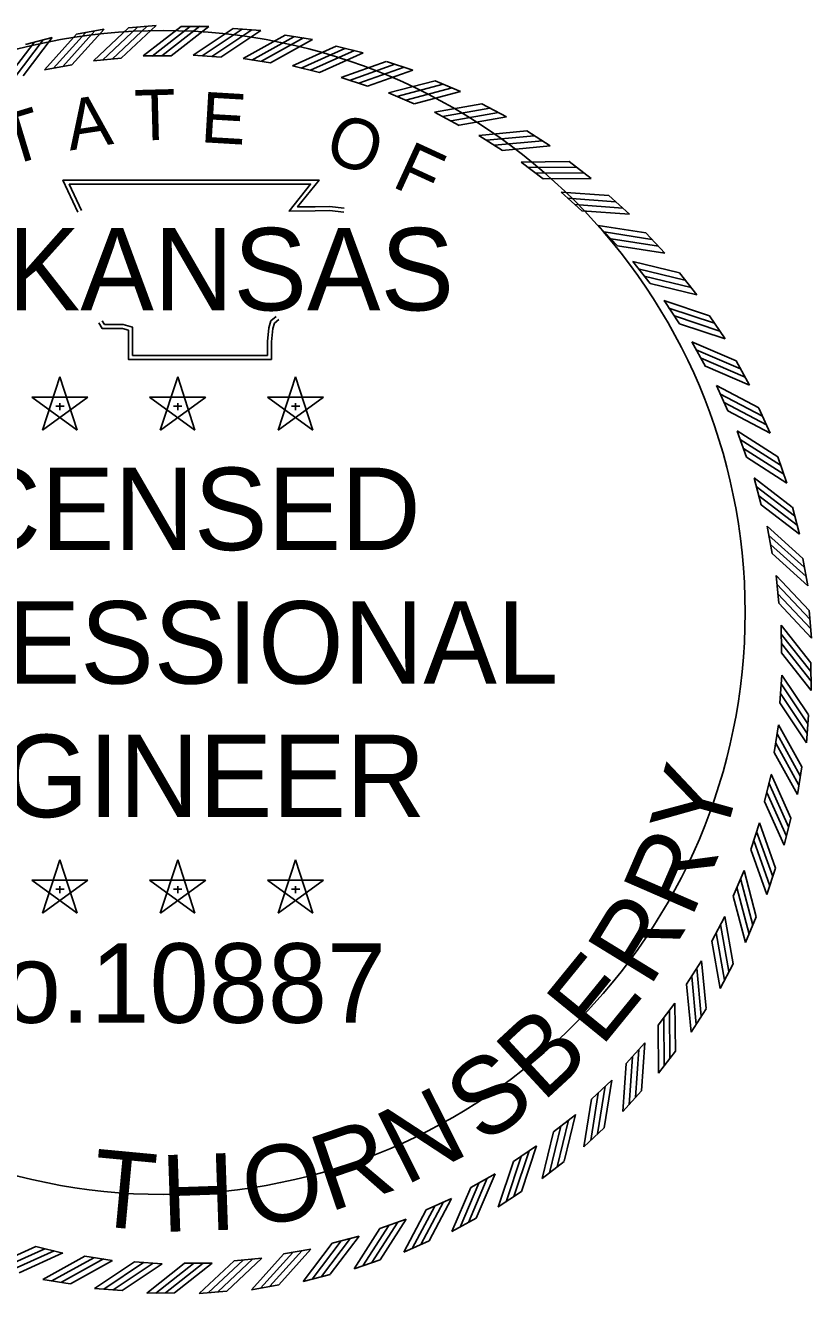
# Model space of a CAD drawing. Extents: x 152 to 3426, y 67 to 2142.
# Drawn here: x 3095.4 to 3247.4, y 306.4 to 551.5 of the extents above; entities that cross this region are included whole.
import ezdxf

# ---------------------------------------------------------------- set-up
doc = ezdxf.new("R2010")
doc.units = 0
doc.layers.add('G-TBLK', color=7, linetype='Continuous')
doc.layers.add('R_Annotation', color=7, linetype='Continuous')

msp = doc.modelspace()

# ---------------------------------------------------------------- linework, layer by layer
at = {"layer": 'G-TBLK'}
msp.add_circle((3122.09, 438.03), 112.43, dxfattribs=at)
at = {"layer": 'R_Annotation'}
for p, q in [((3115.38, 550.96), (3120.73, 551.45)), ((3095.43, 547.73), (3100.62, 549.1)), ((3105.34, 549.76), (3110.62, 550.69)), ((3125.54, 551.26), (3130.91, 551.26)), ((3135.59, 550.85), (3140.95, 550.46)), ((3135.6, 550.86), (3140.95, 550.47)), ((3145.62, 549.55), (3150.92, 548.72)), ((3155.51, 547.43), (3160.73, 546.16)), ((3108.61, 544.6), (3113.97, 545.09)), ((3118.22, 545.55), (3123.6, 545.55)), ((3127.87, 545.7), (3133.24, 545.3)), ((3127.87, 545.7), (3133.24, 545.3)), ((3137.5, 545.05), (3142.82, 544.21)), ((3165.19, 544.49), (3170.28, 542.8)), ((3099.12, 542.86), (3104.42, 543.8)), ((3147.05, 543.61), (3152.27, 542.34)), ((3156.44, 541.39), (3161.54, 539.69)), ((3174.6, 540.77), (3179.53, 538.66)), ((3165.62, 538.4), (3170.56, 536.28)), ((3174.52, 534.66), (3179.27, 532.14)), ((3183.66, 536.28), (3188.4, 533.77)), ((3183.08, 530.2), (3187.61, 527.3)), ((3192.32, 531.06), (3196.84, 528.16)), ((3191.24, 525.04), (3195.51, 521.78)), ((3200.52, 525.14), (3204.79, 521.88)), ((3198.95, 519.23), (3202.94, 515.63)), ((3208.21, 518.56), (3212.19, 514.96)), ((3206.15, 512.81), (3209.83, 508.88)), ((3215.32, 511.37), (3218.99, 507.46)), ((3212.8, 505.81), (3216.14, 501.59)), ((3221.82, 503.62), (3225.16, 499.42)), ((3218.85, 498.28), (3221.83, 493.81)), ((3227.66, 495.36), (3230.63, 490.89)), ((3224.25, 490.29), (3226.85, 485.58)), ((3232.79, 486.64), (3235.39, 481.95)), ((3102.1, 483.56), (3098.74, 473.26)), ((3105.44, 473.26), (3102.1, 483.57)), ((3124.86, 483.56), (3121.5, 473.26)), ((3128.2, 473.26), (3124.86, 483.57)), ((3147.62, 483.56), (3144.26, 473.26)), ((3150.96, 473.26), (3147.62, 483.57)), ((3228.98, 481.87), (3231.18, 476.96)), ((3107.51, 479.62), (3096.67, 479.63)), ((3096.68, 479.62), (3105.44, 473.25)), ((3098.75, 473.26), (3107.52, 479.62)), ((3101.32, 477.89), (3102.93, 477.89)), ((3102.11, 478.47), (3102.11, 477.11)), ((3130.27, 479.62), (3119.43, 479.63)), ((3119.44, 479.62), (3128.2, 473.25)), ((3121.51, 473.26), (3130.28, 479.62)), ((3124.08, 477.89), (3125.69, 477.89)), ((3124.87, 478.47), (3124.87, 477.11)), ((3153.03, 479.62), (3142.19, 479.63)), ((3142.2, 479.62), (3150.96, 473.25)), ((3144.27, 473.26), (3153.04, 479.62)), ((3146.84, 477.89), (3148.45, 477.89)), ((3147.63, 478.47), (3147.63, 477.11)), ((3237.19, 477.53), (3239.39, 472.64)), ((3232.99, 473.09), (3234.78, 468.02)), ((3240.82, 468.09), (3242.6, 463.03)), ((3236.27, 464.01), (3237.64, 458.81)), ((3243.65, 458.38), (3245.02, 453.19)), ((3238.78, 454.69), (3239.72, 449.4)), ((3245.68, 448.47), (3246.61, 443.19)), ((3240.52, 445.2), (3241.01, 439.84)), ((3246.88, 438.43), (3247.37, 433.09)), ((3241.47, 435.59), (3241.52, 430.21)), ((3247.24, 428.32), (3247.29, 422.96)), ((3241.62, 425.94), (3241.22, 420.58)), ((3246.77, 418.22), (3246.38, 412.87)), ((3240.97, 416.31), (3240.13, 411)), ((3239.53, 406.76), (3238.26, 401.54)), ((3245.47, 408.19), (3244.64, 402.89)), ((3237.31, 397.37), (3235.61, 392.27)), ((3243.35, 398.3), (3242.08, 393.09)), ((3102.1, 390.24), (3098.74, 379.94)), ((3105.44, 379.94), (3102.1, 390.25)), ((3124.86, 390.24), (3121.5, 379.94)), ((3128.2, 379.94), (3124.86, 390.25)), ((3147.62, 390.24), (3144.26, 379.94)), ((3150.96, 379.94), (3147.62, 390.25)), ((3234.31, 388.19), (3232.2, 383.25)), ((3240.41, 388.62), (3238.71, 383.53)), ((3107.51, 386.3), (3096.67, 386.31)), ((3096.68, 386.3), (3105.44, 379.93)), ((3098.75, 379.94), (3107.52, 386.3)), ((3102.11, 385.15), (3102.11, 383.79)), ((3130.27, 386.3), (3119.43, 386.31)), ((3119.44, 386.3), (3128.2, 379.93)), ((3121.51, 379.94), (3130.28, 386.3)), ((3124.87, 385.15), (3124.87, 383.79)), ((3153.03, 386.3), (3142.19, 386.31)), ((3142.2, 386.3), (3150.96, 379.93)), ((3144.27, 379.94), (3153.04, 386.3)), ((3147.63, 385.15), (3147.63, 383.79)), ((3101.32, 384.57), (3102.93, 384.57)), ((3124.08, 384.57), (3125.69, 384.57)), ((3146.84, 384.57), (3148.45, 384.57)), ((3230.58, 379.3), (3228.06, 374.54)), ((3236.68, 379.22), (3234.57, 374.28)), ((3226.11, 370.74), (3223.21, 366.21)), ((3232.2, 370.15), (3229.69, 365.41)), ((3220.96, 362.57), (3217.7, 358.3)), ((3226.97, 361.49), (3224.08, 356.97)), ((3215.15, 354.86), (3211.55, 350.87)), ((3221.06, 353.29), (3217.8, 349.02)), ((3208.73, 347.66), (3204.8, 343.98)), ((3214.48, 345.6), (3210.88, 341.62)), ((3201.73, 341.01), (3197.51, 337.67)), ((3207.29, 338.49), (3203.38, 334.82)), ((3194.2, 334.97), (3189.73, 331.98)), ((3199.54, 331.99), (3195.33, 328.66)), ((3186.21, 329.56), (3181.5, 326.96)), ((3191.28, 326.15), (3186.81, 323.18)), ((3177.79, 324.84), (3172.88, 322.63)), ((3182.56, 321.02), (3177.87, 318.42)), ((3169.01, 320.82), (3163.94, 319.03)), ((3159.93, 317.55), (3154.73, 316.18)), ((3173.45, 316.63), (3168.56, 314.43)), ((3102.68, 314.28), (3097.46, 315.55)), ((3112.23, 312.84), (3106.92, 313.68)), ((3150.61, 315.03), (3145.32, 314.1)), ((3121.86, 312.2), (3116.5, 312.59)), ((3131.51, 312.35), (3126.13, 312.3)), ((3141.12, 313.29), (3135.76, 312.8)), ((3164.01, 313), (3158.95, 311.21)), ((3104.11, 308.34), (3098.81, 309.18)), ((3154.3, 310.16), (3149.11, 308.8)), ((3114.14, 307.04), (3108.79, 307.43)), ((3124.24, 306.57), (3118.88, 306.52)), ((3134.35, 306.94), (3129.01, 306.44)), ((3144.39, 308.14), (3139.11, 307.2))]:
    msp.add_line(p, q, dxfattribs=at)
for points in [[(3112.18, 544.95), (3118.95, 551.31)], [(3113.96, 545.1), (3120.73, 551.45)], [(3094.99, 541.72), (3100.62, 549.1)], [(3099.11, 542.86), (3105.33, 549.75)], [(3100.82, 543.14), (3107.04, 550.04)], [(3102.65, 543.51), (3108.86, 550.4)], [(3104.41, 543.8), (3110.63, 550.69)], [(3108.61, 544.59), (3115.37, 550.95)], [(3110.33, 544.74), (3117.1, 551.09)], [(3118.21, 545.54), (3125.54, 551.25)], [(3119.94, 545.53), (3127.26, 551.24)], [(3121.81, 545.57), (3129.13, 551.28)], [(3123.59, 545.55), (3130.91, 551.26)], [(3127.86, 545.69), (3135.59, 550.86)], [(3127.87, 545.69), (3135.59, 550.85)], [(3129.58, 545.55), (3137.31, 550.71)], [(3129.59, 545.55), (3137.31, 550.71)], [(3131.45, 545.46), (3139.18, 550.62)], [(3131.45, 545.45), (3139.17, 550.61)], [(3133.23, 545.31), (3140.96, 550.47)], [(3133.23, 545.31), (3140.95, 550.46)], [(3137.5, 545.05), (3145.62, 549.55)], [(3139.2, 544.76), (3147.32, 549.26)], [(3141.05, 544.51), (3149.17, 549.02)], [(3091.47, 540.77), (3097.1, 548.15)], [(3093.26, 541.28), (3098.89, 548.66)], [(3142.81, 544.22), (3150.93, 548.72)], [(3147.04, 543.61), (3155.5, 547.42)], [(3148.71, 543.18), (3157.18, 547)], [(3150.54, 542.78), (3159, 546.6)], [(3152.27, 542.34), (3160.73, 546.16)], [(3156.43, 541.38), (3165.18, 544.49)], [(3158.07, 540.82), (3166.82, 543.93)], [(3159.85, 540.27), (3168.6, 543.38)], [(3161.54, 539.69), (3170.29, 542.8)], [(3165.61, 538.39), (3174.59, 540.76)], [(3167.19, 537.7), (3176.17, 540.07)], [(3168.92, 537), (3177.9, 539.38)], [(3170.56, 536.29), (3179.54, 538.66)], [(3174.51, 534.66), (3183.65, 536.28)], [(3176.03, 533.83), (3185.17, 535.45)], [(3177.69, 533), (3186.84, 534.62)], [(3179.27, 532.15), (3188.41, 533.77)], [(3183.07, 530.19), (3192.31, 531.06)], [(3184.51, 529.25), (3193.76, 530.11)], [(3186.11, 528.28), (3195.35, 529.14)], [(3187.6, 527.3), (3196.85, 528.16)], [(3191.23, 525.04), (3200.52, 525.14)], [(3192.59, 523.98), (3201.88, 524.08)], [(3194.1, 522.88), (3203.38, 522.98)], [(3105.55, 515.34), (3102.69, 521.54), (3152.18, 521.57), (3148.04, 516.37), (3151.41, 516.42), (3154.21, 516.45), (3157.02, 516.15)], [(3106.26, 515.67), (3103.92, 520.76), (3150.55, 520.78), (3146.4, 515.57), (3151.42, 515.63), (3154.18, 515.67), (3156.94, 515.37)], [(3195.51, 521.79), (3204.79, 521.88)], [(3198.94, 519.23), (3208.2, 518.56)], [(3200.21, 518.06), (3209.47, 517.39)], [(3201.62, 516.84), (3210.88, 516.17)], [(3202.94, 515.63), (3212.2, 514.96)], [(3206.14, 512.81), (3215.32, 511.37)], [(3207.31, 511.54), (3216.49, 510.1)], [(3208.62, 510.21), (3217.79, 508.77)], [(3209.83, 508.89), (3219, 507.46)], [(3212.79, 505.81), (3221.81, 503.62)], [(3213.85, 504.45), (3222.87, 502.26)], [(3215.04, 503.01), (3224.06, 500.83)], [(3216.14, 501.6), (3225.16, 499.41)], [(3218.84, 498.29), (3227.65, 495.36)], [(3143.89, 495.21), (3142.85, 494.37), (3142.48, 493.04), (3142.19, 490.37), (3142.19, 487.69), (3116.14, 487.69), (3116.14, 491.52), (3116.14, 493.13), (3114.35, 493.68), (3110.72, 493.68), (3110.26, 494.39)], [(3219.78, 496.84), (3228.59, 493.92)], [(3220.85, 495.31), (3229.66, 492.39)], [(3144.38, 494.61), (3143.54, 493.92), (3143.26, 492.89), (3142.98, 490.33), (3142.98, 486.91), (3115.35, 486.91), (3115.35, 491.52), (3115.35, 492.55), (3114.23, 492.89), (3110.3, 492.89), (3109.6, 493.96)], [(3221.83, 493.82), (3230.64, 490.89)], [(3224.24, 490.29), (3232.78, 486.65)], [(3225.06, 488.77), (3233.6, 485.13)], [(3226, 487.16), (3234.54, 483.52)], [(3226.85, 485.59), (3235.39, 481.94)], [(3228.97, 481.87), (3237.18, 477.54)], [(3229.66, 480.29), (3237.87, 475.96)], [(3230.46, 478.61), (3238.67, 474.27)], [(3231.18, 476.97), (3239.39, 472.64)], [(3232.98, 473.1), (3240.81, 468.1)], [(3233.54, 471.46), (3241.37, 466.46)], [(3234.2, 469.72), (3242.03, 464.72)], [(3234.79, 468.03), (3242.61, 463.03)], [(3236.26, 464.02), (3243.64, 458.39)], [(3236.68, 462.34), (3244.07, 456.72)], [(3237.2, 460.55), (3244.58, 454.92)], [(3237.64, 458.82), (3245.02, 453.19)], [(3238.78, 454.7), (3245.67, 448.48)], [(3239.06, 452.99), (3245.95, 446.78)], [(3239.42, 451.17), (3246.32, 444.95)], [(3239.72, 449.4), (3246.61, 443.19)], [(3240.51, 445.2), (3246.87, 438.44)], [(3240.66, 443.48), (3247.01, 436.72)], [(3240.87, 441.63), (3247.23, 434.86)], [(3241.02, 439.85), (3247.37, 433.08)], [(3241.46, 435.6), (3247.24, 428.33)], [(3241.46, 433.87), (3247.24, 426.6)], [(3241.52, 432.01), (3247.3, 424.74)], [(3241.52, 430.22), (3247.3, 422.95)], [(3241.47, 424.23), (3246.63, 416.51)], [(3241.61, 425.95), (3246.77, 418.23)], [(3241.37, 422.36), (3246.53, 414.64)], [(3241.23, 420.58), (3246.38, 412.86)], [(3240.68, 414.61), (3245.18, 406.49)], [(3240.97, 416.32), (3245.47, 408.2)], [(3240.43, 412.77), (3244.93, 404.65)], [(3240.14, 411), (3244.64, 402.88)], [(3239.53, 406.77), (3243.34, 398.31)], [(3239.1, 405.1), (3242.92, 396.63)], [(3238.7, 403.28), (3242.52, 394.81)], [(3238.26, 401.54), (3242.08, 393.08)], [(3237.3, 397.38), (3240.41, 388.63)], [(3236.74, 395.75), (3239.85, 387)], [(3235.61, 392.27), (3238.72, 383.52)], [(3236.19, 393.96), (3239.3, 385.21)], [(3234.31, 388.2), (3236.68, 379.23)], [(3232.92, 384.89), (3235.29, 375.91)], [(3233.62, 386.62), (3235.99, 377.64)], [(3232.21, 383.25), (3234.58, 374.28)], [(3229.75, 377.78), (3231.37, 368.64)], [(3230.57, 379.3), (3232.2, 370.16)], [(3228.92, 376.12), (3230.54, 366.98)], [(3228.07, 374.55), (3229.69, 365.4)], [(3226.11, 370.74), (3226.97, 361.5)], [(3224.2, 367.71), (3225.06, 358.46)], [(3225.17, 369.3), (3226.03, 360.05)], [(3223.22, 366.21), (3224.08, 356.96)], [(3219.9, 361.22), (3220, 351.93)], [(3220.96, 362.58), (3221.06, 353.3)], [(3217.7, 358.3), (3217.8, 349.02)], [(3218.8, 359.71), (3218.9, 350.43)], [(3213.98, 353.6), (3213.31, 344.34)], [(3215.15, 354.87), (3214.48, 345.61)], [(3211.55, 350.88), (3210.88, 341.62)], [(3212.76, 352.19), (3212.09, 342.93)], [(3207.46, 346.5), (3206.02, 337.33)], [(3208.73, 347.67), (3207.29, 338.5)], [(3204.81, 343.98), (3203.38, 334.81)], [(3206.13, 345.19), (3204.69, 336.02)], [(3201.73, 341.02), (3199.54, 332)], [(3198.93, 338.77), (3196.74, 329.75)], [(3200.37, 339.96), (3198.18, 330.94)], [(3197.52, 337.67), (3195.33, 328.65)], [(3192.76, 334.03), (3189.83, 325.22)], [(3194.21, 334.97), (3191.28, 326.16)], [(3189.74, 331.98), (3186.81, 323.17)], [(3191.23, 332.96), (3188.31, 324.15)], [(3184.69, 328.75), (3181.05, 320.21)], [(3186.21, 329.57), (3182.57, 321.03)], [(3181.51, 326.96), (3177.86, 318.42)], [(3183.08, 327.81), (3179.44, 319.27)], [(3176.21, 324.15), (3171.88, 315.94)], [(3177.79, 324.84), (3173.46, 316.63)], [(3172.89, 322.63), (3168.56, 314.42)], [(3174.53, 323.35), (3170.19, 315.14)], [(3163.95, 319.03), (3158.95, 311.2)], [(3165.64, 319.61), (3160.64, 311.78)], [(3167.38, 320.27), (3162.38, 312.44)], [(3169.02, 320.83), (3164.02, 313)], [(3154.74, 316.17), (3149.11, 308.79)], [(3156.47, 316.61), (3150.84, 309.23)], [(3158.26, 317.13), (3152.63, 309.74)], [(3159.94, 317.55), (3154.31, 310.17)], [(3097.46, 315.55), (3089, 311.73)], [(3099.2, 315.11), (3090.73, 311.3)], [(3101.02, 314.71), (3092.55, 310.89)], [(3102.69, 314.29), (3094.23, 310.47)], [(3106.92, 313.67), (3098.8, 309.17)], [(3145.32, 314.09), (3139.1, 307.2)], [(3147.09, 314.39), (3140.87, 307.49)], [(3148.91, 314.75), (3142.7, 307.86)], [(3150.62, 315.04), (3144.4, 308.14)], [(3108.68, 313.38), (3100.56, 308.88)], [(3110.53, 313.13), (3102.41, 308.63)], [(3112.24, 312.85), (3104.12, 308.34)], [(3116.5, 312.59), (3108.78, 307.43)], [(3118.28, 312.44), (3110.56, 307.28)], [(3120.14, 312.34), (3112.42, 307.19)], [(3121.87, 312.2), (3114.15, 307.04)], [(3126.14, 312.29), (3118.87, 306.52)], [(3127.93, 312.29), (3120.66, 306.52)], [(3129.79, 312.35), (3122.52, 306.57)], [(3131.52, 312.35), (3124.25, 306.57)], [(3135.77, 312.8), (3129, 306.44)], [(3137.55, 312.94), (3130.78, 306.59)], [(3139.4, 313.16), (3132.64, 306.8)], [(3141.12, 313.3), (3134.36, 306.94)]]:
    msp.add_lwpolyline(points, dxfattribs=at)

# ---------------------------------------------------------------- texts
for s, height, rotation, p in [('T', 9.77, 1.4789, (3116.63, 529.18)), ('T', 9.76, 1.4789, (3116.65, 529.2)), ('A', 9.76, 8.6788, (3104.04, 527.26)), ('E', 9.76, 356.672, (3129.14, 528.9)), ('T', 9.76, 16.9015, (3092.19, 524.16)), ('O', 9.76, 341.2218, (3152.84, 525.56)), ('F', 9.76, 335.3628, (3166, 520.41)), ('Y', 14.83, 74.5264, (3230.2, 393.01)), ('R', 14.83, 66.5008, (3224.09, 378.71)), ('R', 14.83, 58.4752, (3216.04, 365.4)), ('E', 14.83, 50.8144, (3206.7, 353.86)), ('B', 14.83, 42.7888, (3195.36, 343.23)), ('S', 14.83, 35.4928, (3183.84, 335.02)), ('N', 14.83, 26.7376, (3168.8, 327.19)), ('R', 14.83, 18.712, (3154.1, 322.11)), ('O', 14.83, 10.6864, (3138.84, 319.12)), ('T', 14.83, 354.6351, (3107.82, 319.66)), ('H', 14.83, 1.9312, (3121.89, 318.34))]:
    msp.add_text(s, height=height, rotation=rotation, dxfattribs=at).set_placement(p)
for s, height, p in [('ARKANSAS', 15.932, (3062.24, 496.39)), ('LICENSED', 15.932, (3065.27, 450.08)), ('PROFESSIONAL', 15.9321, (3032.65, 424.28)), ('ENGINEER', 15.932, (3061.48, 398.49)), ('No.10887', 15.363, (3076.04, 358.76))]:
    msp.add_text(s, height=height, dxfattribs=at).set_placement(p)

doc.saveas('drawing.dxf')
